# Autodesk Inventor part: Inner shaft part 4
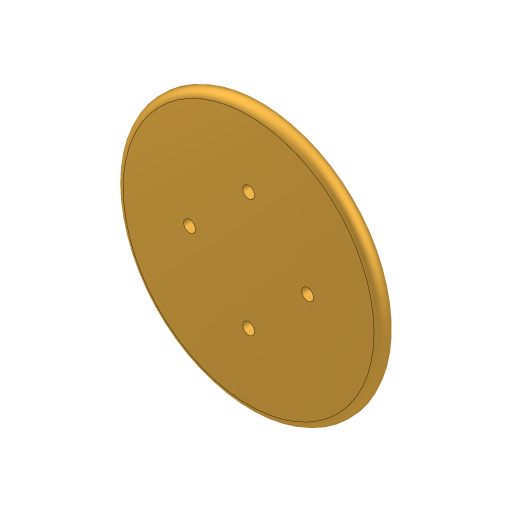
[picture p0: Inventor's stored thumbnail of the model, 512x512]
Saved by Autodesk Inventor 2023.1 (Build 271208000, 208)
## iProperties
Created: 2020-02
Part Number: Inner shaft part 4
Material: Brass, Soft Yellow
Document SubType Name: Modeling
Designer: ftrauzettel
Density: 8.47 g/cm^3
Appearance: Brass - Satin
Sending System: SolidWorks 2016
Last Author: Pam
Last Saved: 2020-02-24
Author: ftrauzettel
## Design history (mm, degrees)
feature "Tap Drill Slot for M2 Tap1"
body "Solid1"
